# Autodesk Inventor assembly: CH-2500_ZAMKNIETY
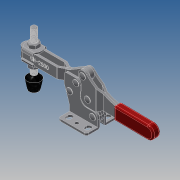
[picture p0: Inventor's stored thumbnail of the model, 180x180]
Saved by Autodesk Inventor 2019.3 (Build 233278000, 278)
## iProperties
Company: Î¢ÈíÖÐ¹ú
Created: 2012-09
Part Number: CH-2500_ZAMKNIETY
Material: Ogólny
Description: STEP AP203
Document SubType Name: Assembly
Designer: CADENGINEERING4
Sending System: SolidWorks 2010
Preprocessor: SwSTEP 2.0
Title: CH-2500.STEP
Author: Î¢ÈíÓÃ»§
Revision Number: ÈÎºÎ
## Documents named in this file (12)
- E:\STRONA\Horizontal toggle clamp\CH-2500\CH-2500_ZAMKNIETY.iam
- E:\STRONA\Horizontal toggle clamp\CH-2500\CH-36092M-06___.ipt
- E:\STRONA\Horizontal toggle clamp\CH-2500\CH-2500-06___.ipt
- E:\STRONA\Horizontal toggle clamp\CH-2500\CH-2500-03___.ipt
- E:\STRONA\Horizontal toggle clamp\CH-2500\CH-FC-56300___.ipt
- E:\STRONA\Horizontal toggle clamp\CH-2500\CH-2500-01___.ipt
- E:\STRONA\Horizontal toggle clamp\CH-2500\CH-11401-05___.ipt
- E:\STRONA\Horizontal toggle clamp\CH-2500\CH-2500-02___.ipt
- E:\STRONA\Horizontal toggle clamp\CH-2500\FW516___.ipt
- E:\STRONA\Horizontal toggle clamp\CH-2500\CH-2500-04___.ipt
- E:\STRONA\Horizontal toggle clamp\CH-2500\CH-FC-56300-02___.ipt
- E:\STRONA\Horizontal toggle clamp\CH-2500\CH-2500-05___.ipt
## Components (20 placed, 20 different names)
1. CH-36092M-06____1 — Zestawiające:24, Równoległe:3, Zestawiające:25
2. CH-2500-06____2 — Zestawiające:33, Zestawiające:34, Zestawiające:35
3. CH-2500-03____3 — Zestawiające:12, Zestawiające:13, Zestawiające:14, Zestawiające:17, Zestawiające:18, Zestawiające:25, Zestawiające:26, Zestawiające:27, Zestawiające:36, Zestawiające:37, Przejściowe:1
4. CH-FC-56300____4 — Równoległe:2, Zestawiające:3, Zestawiające:4, Zestawiające:5, Zestawiające:6, Zestawiające:11
5. CH-2500-01____5 — Zestawiające:15, Zestawiające:16, Zestawiające:19, Zestawiające:20, Zestawiające:21, Zestawiające:22, Zestawiające:28, Zestawiające:29, Zestawiające:30, Zestawiające:31, Zestawiające:32, Zestawiające:34, Zestawiające:35, Przejściowe:1
6. CH-11401-05____6 — Zestawiające:28, Zestawiające:29
7. CH-2500-02____7 — Zestawiające:1, Kątowe:1, Zestawiające:9, Zestawiające:10, Zestawiające:11, Zestawiające:32, Zestawiające:33, Zestawiające:38
8. FW516____8 — Zestawiające:2, Równoległe:1, Zestawiające:6, Zestawiające:7, Zestawiające:10
9. CH-36092M-06____9 — Zestawiające:15, Zestawiające:16
10. CH-2500-04____10 — Zestawiające:21, Zestawiające:22, Zestawiające:23, Zestawiające:24, Równoległe:3, Zestawiające:26
11. CH-2500-06____11 — Zestawiające:30, Zestawiające:31
12. CH-2500-06____12 — Zestawiające:19, Zestawiające:20
13. CH-FC-56300-02____13 — Zestawiające:4, Zestawiające:8
14. CH-2500-06____14 — Zestawiające:36, Zestawiające:37, Zestawiające:38
15. FW516____15 — Równoległe:1, Zestawiające:3, Zestawiające:8, Zestawiające:9
16. CH-36092M-06____16 — Zestawiające:17, Zestawiające:18
17. CH-2500-05____17 — Zestawiające:12, Zestawiające:13, Zestawiające:14
18. CH-FC-56300-02____18 — Równoległe:2, Zestawiające:5, Zestawiające:7
19. CH-2500-06____19 — Zestawiające:23, Zestawiające:27
20. CH-36092M-06____20
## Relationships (43: Mate 38, Flush 3, Angle 1, Transitional 1)
- Zestawiające:1 [Mate]: CH-2500-02____7
- Kątowe:1 [Angle]: CH-2500-02____7
- Zestawiające:2 [Mate]: FW516____8
- Równoległe:1 [Flush]: FW516____8 ↔ FW516____15
- Równoległe:2 [Flush]: CH-FC-56300____4 ↔ CH-FC-56300-02____18
- Zestawiające:3 [Mate]: CH-FC-56300____4 ↔ FW516____15
- Zestawiające:4 [Mate]: CH-FC-56300____4 ↔ CH-FC-56300-02____13
- Zestawiające:5 [Mate]: CH-FC-56300____4 ↔ CH-FC-56300-02____18
- Zestawiające:6 [Mate]: CH-FC-56300____4 ↔ FW516____8
- Zestawiające:7 [Mate]: FW516____8 ↔ CH-FC-56300-02____18
- Zestawiające:8 [Mate]: CH-FC-56300-02____13 ↔ FW516____15
- Zestawiające:9 [Mate]: CH-2500-02____7 ↔ FW516____15
- Zestawiające:10 [Mate]: CH-2500-02____7 ↔ FW516____8
- Zestawiające:11 [Mate]: CH-FC-56300____4 ↔ CH-2500-02____7
- Zestawiające:12 [Mate]: CH-2500-03____3 ↔ CH-2500-05____17
- Zestawiające:13 [Mate]: CH-2500-03____3 ↔ CH-2500-05____17
- Zestawiające:14 [Mate]: CH-2500-03____3 ↔ CH-2500-05____17
- Zestawiające:15 [Mate]: CH-2500-01____5 ↔ CH-36092M-06____9
- Zestawiające:16 [Mate]: CH-2500-01____5 ↔ CH-36092M-06____9
- Zestawiające:17 [Mate]: CH-2500-03____3 ↔ CH-36092M-06____16
- Zestawiające:18 [Mate]: CH-2500-03____3 ↔ CH-36092M-06____16
- Zestawiające:19 [Mate]: CH-2500-01____5 ↔ CH-2500-06____12
- Zestawiające:20 [Mate]: CH-2500-01____5 ↔ CH-2500-06____12
- Zestawiające:21 [Mate]: CH-2500-01____5 ↔ CH-2500-04____10
- Zestawiające:22 [Mate]: CH-2500-01____5 ↔ CH-2500-04____10
- Zestawiające:23 [Mate]: CH-2500-04____10 ↔ CH-2500-06____19
- Zestawiające:24 [Mate]: CH-36092M-06____1 ↔ CH-2500-04____10
- Równoległe:3 [Flush]: CH-36092M-06____1 ↔ CH-2500-04____10
- Zestawiające:25 [Mate]: CH-36092M-06____1 ↔ CH-2500-03____3
- Zestawiające:26 [Mate]: CH-2500-03____3 ↔ CH-2500-04____10
- Zestawiające:27 [Mate]: CH-2500-03____3 ↔ CH-2500-06____19
- Zestawiające:28 [Mate]: CH-2500-01____5 ↔ CH-11401-05____6
- Zestawiające:29 [Mate]: CH-2500-01____5 ↔ CH-11401-05____6
- Zestawiające:30 [Mate]: CH-2500-01____5 ↔ CH-2500-06____11
- Zestawiające:31 [Mate]: CH-2500-01____5 ↔ CH-2500-06____11
- Zestawiające:32 [Mate]: CH-2500-01____5 ↔ CH-2500-02____7
- Zestawiające:33 [Mate]: CH-2500-06____2 ↔ CH-2500-02____7
- Zestawiające:34 [Mate]: CH-2500-06____2 ↔ CH-2500-01____5
- Zestawiające:35 [Mate]: CH-2500-06____2 ↔ CH-2500-01____5
- Zestawiające:36 [Mate]: CH-2500-03____3 ↔ CH-2500-06____14
- Zestawiające:37 [Mate]: CH-2500-03____3 ↔ CH-2500-06____14
- Zestawiające:38 [Mate]: CH-2500-02____7 ↔ CH-2500-06____14
- Przejściowe:1 [Transitional]: CH-2500-03____3 ↔ CH-2500-01____5
